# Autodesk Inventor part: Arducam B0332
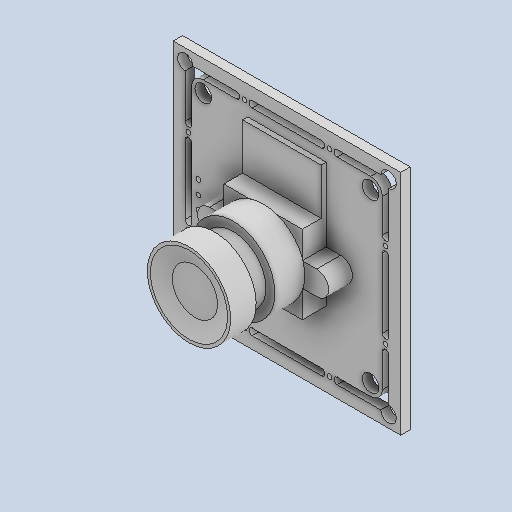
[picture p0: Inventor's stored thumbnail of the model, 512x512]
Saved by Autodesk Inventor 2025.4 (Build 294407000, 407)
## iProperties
Created: 2026-09
Part Number: Arducam B0332
Material: Generic
Document SubType Name: Modeling
Designer: AdminForWorker
Density: 1 g/cm^3
Appearance: Default
Title: Arducam B0332 v1
Author: AdminForWorker
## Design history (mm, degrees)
feature "Body1"
body "Solid1"
